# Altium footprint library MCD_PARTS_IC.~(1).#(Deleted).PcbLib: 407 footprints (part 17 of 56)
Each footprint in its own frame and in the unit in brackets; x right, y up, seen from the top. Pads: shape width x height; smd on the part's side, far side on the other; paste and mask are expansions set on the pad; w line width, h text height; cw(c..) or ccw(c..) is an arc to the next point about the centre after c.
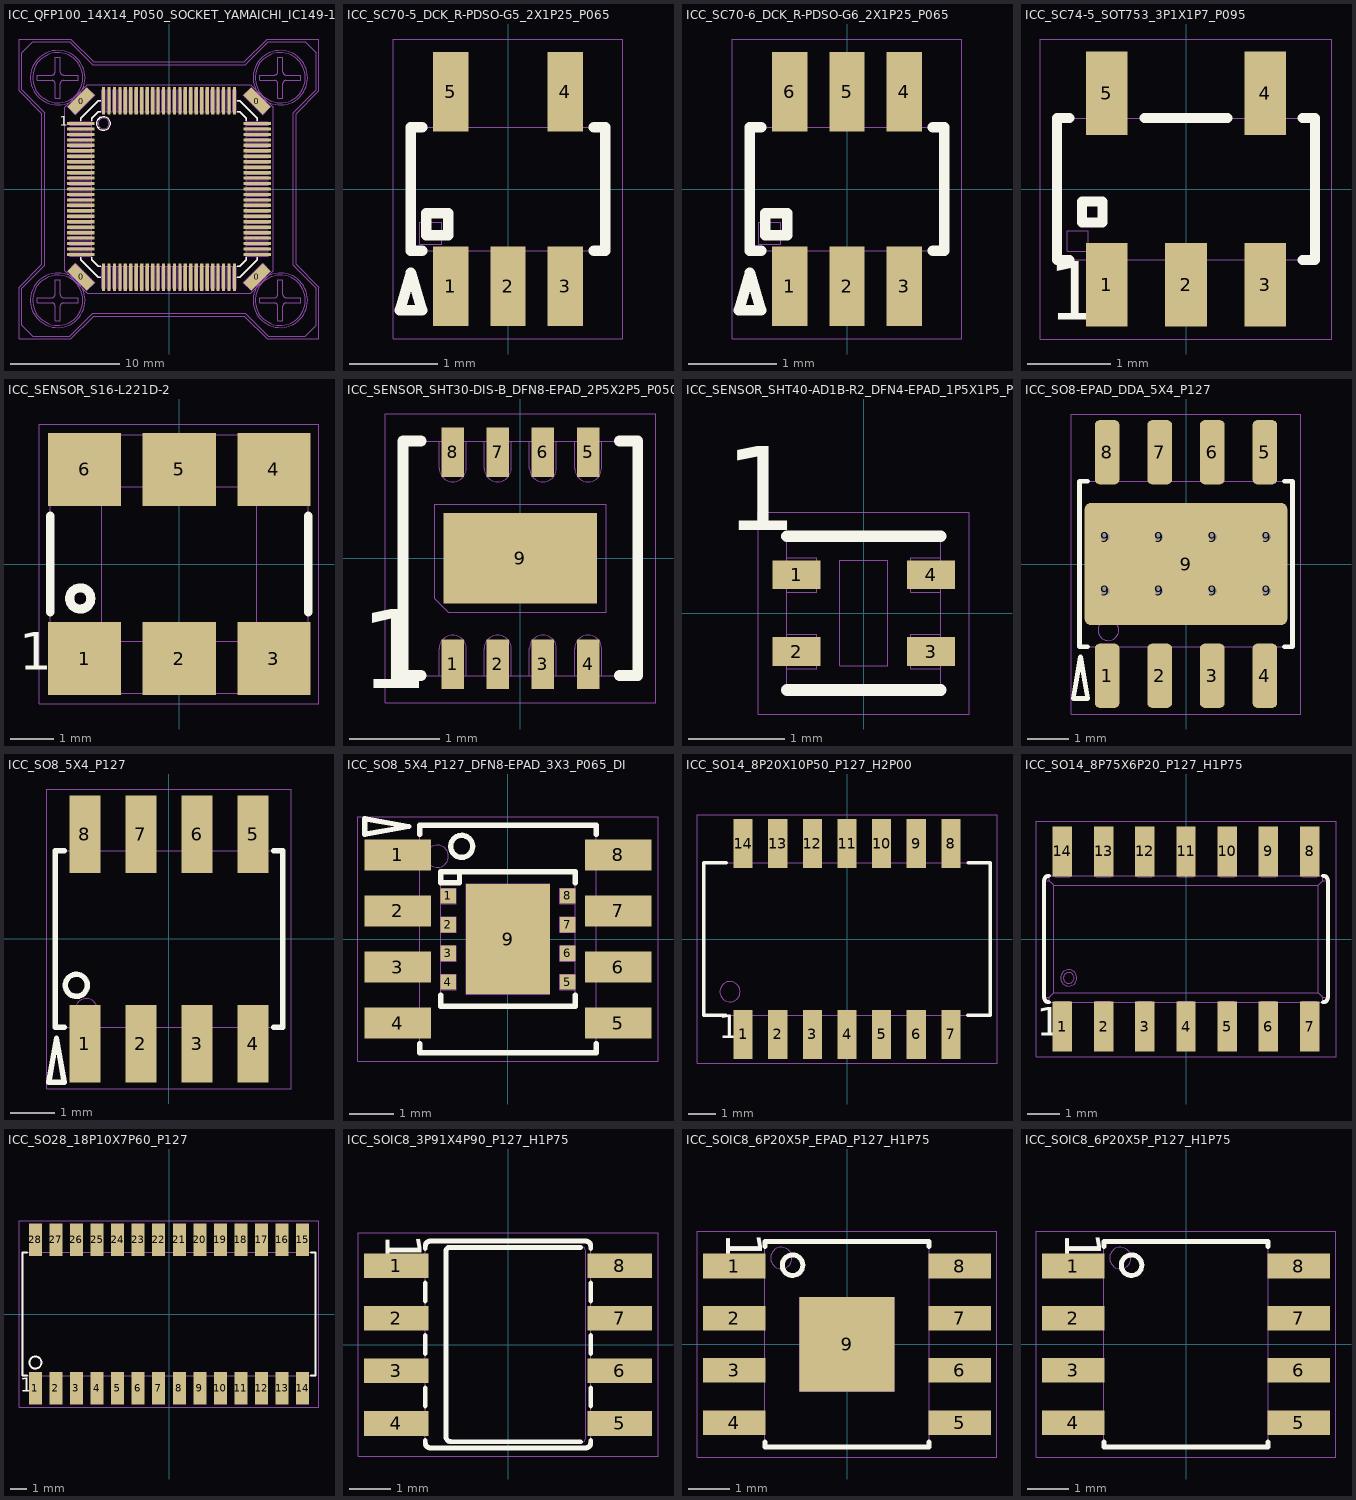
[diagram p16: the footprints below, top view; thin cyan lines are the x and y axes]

## ICC_QFP100_14X14_P050_SOCKET_YAMAICHI_IC149-100-025-B5__CUSTOM-FOR-DI__MB1581A [mm]
height 13.2
pads (104):
  rect 1x2.5 smd rot 45 mask+0.05: 0(-8.061,-8.061) 0(8.061,8.061)
  rect 1x2.5 smd rot 135 mask+0.05: 0(-8.061,8.061) 0(8.061,-8.061)
  rect 2.5x0.3 smd mask+0.05: 1(-8.1,6) 2(-8.1,5.5) 3(-8.1,5) 4(-8.1,4.5) 5(-8.1,4) 6(-8.1,3.5) 7(-8.1,3) 8(-8.1,2.5) 9(-8.1,2) 10(-8.1,1.5) 11(-8.1,1) 12(-8.1,0.5) 13(-8.1,0) 14(-8.1,-0.5) 15(-8.1,-1) 16(-8.1,-1.5) 17(-8.1,-2) 18(-8.1,-2.5) 19(-8.1,-3) 20(-8.1,-3.5) 21(-8.1,-4) 22(-8.1,-4.5) 23(-8.1,-5) 24(-8.1,-5.5) 25(-8.1,-6) 51(8.1,-6) 52(8.1,-5.5) 53(8.1,-5) 54(8.1,-4.5) 55(8.1,-4) 56(8.1,-3.5) 57(8.1,-3) 58(8.1,-2.5) 59(8.1,-2) 60(8.1,-1.5) 61(8.1,-1) 62(8.1,-0.5) 63(8.1,0) 64(8.1,0.5) 65(8.1,1) 66(8.1,1.5) 67(8.1,2) 68(8.1,2.5) 69(8.1,3) 70(8.1,3.5) 71(8.1,4) 72(8.1,4.5) 73(8.1,5) 74(8.1,5.5) 75(8.1,6)
  rect 0.3x2.5 smd mask+0.05: 26(-6,-8.1) 27(-5.5,-8.1) 28(-5,-8.1) 29(-4.5,-8.1) 30(-4,-8.1) 31(-3.5,-8.1) 32(-3,-8.1) 33(-2.5,-8.1) 34(-2,-8.1) 35(-1.5,-8.1) 36(-1,-8.1) 37(-0.5,-8.1) 38(0,-8.1) 39(0.5,-8.1) 40(1,-8.1) 41(1.5,-8.1) 42(2,-8.1) 43(2.5,-8.1) 44(3,-8.1) 45(3.5,-8.1) 46(4,-8.1) 47(4.5,-8.1) 48(5,-8.1) 49(5.5,-8.1) 50(6,-8.1) 76(6,8.1) 77(5.5,8.1) 78(5,8.1) 79(4.5,8.1) 80(4,8.1) 81(3.5,8.1) 82(3,8.1) 83(2.5,8.1) 84(2,8.1) 85(1.5,8.1) 86(1,8.1) 87(0.5,8.1) 88(0,8.1) 89(-0.5,8.1) 90(-1,8.1) 91(-1.5,8.1) 92(-2,8.1) 93(-2.5,8.1) 94(-3,8.1) 95(-3.5,8.1) 96(-4,8.1) 97(-4.5,8.1) 98(-5,8.1) 99(-5.5,8.1) 100(-6,8.1)
Top Overlay:
  circle w0.12: c-6,6 r0.625
  lines w0.12: -8.1,-6.275 -8.1,-6.475 -6.475,-8.1 -6.275,-8.1 ; -8.1,6.275 -8.1,6.475 -6.475,8.1 -6.275,8.1 ; -7.1,-6.275 -7.1,-6.5 -6.5,-7.1 -6.275,-7.1 ; -7.1,6.275 -7.1,6.5 -6.5,7.1 -6.275,7.1 ; 6.275,-8.1 6.475,-8.1 8.1,-6.475 8.1,-6.275 ; 6.275,-7.1 6.5,-7.1 7.1,-6.5 7.1,-6.275 ; 6.275,7.1 6.5,7.1 7.1,6.5 7.1,6.275 ; 6.275,8.1 6.475,8.1 8.1,6.475 8.1,6.275
  text "1" at -10,5.5 h1.5
M7-Top Info:
  lines w0.01: -13.75,-13.75 -13.75,-9.1 -13.75,-9 -11.65,-6.9 -11.65,0 -11.65,6.9 -13.75,9 -13.75,9.1 -13.75,13.75 -9.1,13.75 -9,13.75 -6.9,11.65 0,11.65 6.9,11.65 9,13.75 9.1,13.75 13.75,13.75 13.75,9.1 13.75,9 11.65,6.9 11.65,0 11.65,-6.9 13.75,-9 13.75,-9.1 13.75,-13.75 9.1,-13.75 9,-13.75 6.9,-11.65 0,-11.65 -6.9,-11.65 -9,-13.75 -9.1,-13.75 -13.75,-13.75 ; -9.575,-7.475 -9.575,-6.2 -9.575,6.225 -9.575,7.475 -7.475,9.575 -6.2,9.575 6.225,9.575 7.475,9.575 9.575,7.475 9.575,6.2 9.575,-6.225 9.575,-7.475 7.475,-9.575 -6.225,-9.575 -7.475,-9.575 -9.575,-7.475
  text "AREA AUTHORIZED FOR COMPONENTS LOWER THAN 3.5MM" at -13.2,10.275 h0.7
  text "AREA AUTHORIZED FOR COMPONENTS LOWER THAN 3.5MM" at -10.275,-13.2 h0.7
  text "AREA AUTHORIZED FOR COMPONENTS LOWER THAN 3.5MM" at 10.275,13.2 h0.7
  text "AREA AUTHORIZED FOR COMPONENTS LOWER THAN 3.5MM" at 13.2,-10.275 h0.7
M14-Top Assembly:
  drawing of 869 lines, arcs and shapes, not listed
  text "100" at -5.325,8.075 h1
  text "76" at 6.45,8.075 h1
  text "75" at 8.075,5.525 h1
  text "51" at 8.075,-6.4 h1
  text "50" at 5.55,-8.075 h1
  text "26" at -6.45,-8.075 h1
  text "1" at -8.075,6.125 h1
  text "'.Designator'" at -2,-0.5 h0.75
  text "25" at -8.075,-5.55 h1
M16-Top Courtyard:
  lines w0.01: -13.75,-13.75 -9.1,-13.75 -9,-13.75 -6.9,-11.65 0,-11.65 6.9,-11.65 9,-13.75 9.1,-13.75 13.75,-13.75 13.75,-9.1 13.75,-9 11.65,-6.9 11.65,0 11.65,6.9 13.75,9 13.75,9.1 13.75,13.75 9.1,13.75 9,13.75 6.9,11.65 0,11.65 -6.9,11.65 -9,13.75 -9.1,13.75 -13.75,13.75 -13.75,9.1 -13.75,9 -11.65,6.9 -11.65,0 -11.65,-6.9 -13.75,-9 -13.75,-9.1 -13.75,-13.75 ; -9.575,-7.475 -7.475,-9.575 -6.225,-9.575 7.475,-9.575 9.575,-7.475 9.575,-6.225 9.575,6.2 9.575,7.475 7.475,9.575 6.225,9.575 -6.2,9.575 -7.475,9.575 -9.575,7.475 -9.575,6.225 -9.575,-6.2 -9.575,-7.475
  text "AREA AUTHORIZED FOR COMPONENTS LOWER THAN 3.5MM" at 13.2,-10.275 h0.7
  text "AREA AUTHORIZED FOR COMPONENTS LOWER THAN 3.5MM" at 10.275,13.2 h0.7
  text "AREA AUTHORIZED FOR COMPONENTS LOWER THAN 3.5MM" at -10.275,-13.2 h0.7
  text "AREA AUTHORIZED FOR COMPONENTS LOWER THAN 3.5MM" at -13.2,10.275 h0.7
3D body "LQFP100_05.STEP": height 7.1, standoff 5.5, extent -8,-8 8,8
3D body: height 11, standoff 3.5, extent 0,-13.5 13.5,13.5
3D body: height 11, standoff 3.5, extent -13.5,-13.5 0,13.5
3D body: height 0.2, standoff 0, extent -9.1,3.85 -8.1,4.15
3D body: height 0.2, standoff 0, extent -9.1,4.35 -8.1,4.65
3D body: height 0.2, standoff 0, extent -9.1,4.85 -8.1,5.15
3D body: height 0.2, standoff 0, extent -9.1,5.35 -8.1,5.65
3D body: height 0.2, standoff 0, extent -9.1,5.85 -8.1,6.15
3D body: height 0.2, standoff 0, extent -9.1,1.35 -8.1,1.65
3D body: height 0.2, standoff 0, extent -9.1,1.85 -8.1,2.15
3D body: height 0.2, standoff 0, extent -9.1,2.35 -8.1,2.65
3D body: height 0.2, standoff 0, extent -9.1,2.85 -8.1,3.15
3D body: height 0.2, standoff 0, extent -9.1,3.35 -8.1,3.65
3D body: height 0.2, standoff 0, extent -9.1,-1.15 -8.1,-0.85
3D body: height 0.2, standoff 0, extent -9.1,-0.65 -8.1,-0.35
3D body: height 0.2, standoff 0, extent -9.1,-0.15 -8.1,0.15
3D body: height 0.2, standoff 0, extent -9.1,0.35 -8.1,0.65
3D body: height 0.2, standoff 0, extent -9.1,0.85 -8.1,1.15
3D body: height 0.2, standoff 0, extent -9.1,-3.65 -8.1,-3.35
3D body: height 0.2, standoff 0, extent -9.1,-3.15 -8.1,-2.85
3D body: height 0.2, standoff 0, extent -9.1,-2.65 -8.1,-2.35
3D body: height 0.2, standoff 0, extent -9.1,-2.15 -8.1,-1.85
3D body: height 0.2, standoff 0, extent -9.1,-1.65 -8.1,-1.35
3D body: height 0.2, standoff 0, extent -9.1,-6.15 -8.1,-5.85
3D body: height 0.2, standoff 0, extent -9.1,-5.65 -8.1,-5.35
3D body: height 0.2, standoff 0, extent -9.1,-5.15 -8.1,-4.85
3D body: height 0.2, standoff 0, extent -9.1,-4.65 -8.1,-4.35
3D body: height 0.2, standoff 0, extent -9.1,-4.15 -8.1,-3.85
3D body: height 0.2, standoff 0, extent -4.15,-9.1 -3.85,-8.1
3D body: height 0.2, standoff 0, extent -4.65,-9.1 -4.35,-8.1
3D body: height 0.2, standoff 0, extent -5.15,-9.1 -4.85,-8.1
3D body: height 0.2, standoff 0, extent -5.65,-9.1 -5.35,-8.1
3D body: height 0.2, standoff 0, extent -6.15,-9.1 -5.85,-8.1
3D body: height 0.2, standoff 0, extent -1.65,-9.1 -1.35,-8.1
3D body: height 0.2, standoff 0, extent -2.15,-9.1 -1.85,-8.1
3D body: height 0.2, standoff 0, extent -2.65,-9.1 -2.35,-8.1
3D body: height 0.2, standoff 0, extent -3.15,-9.1 -2.85,-8.1
3D body: height 0.2, standoff 0, extent -3.65,-9.1 -3.35,-8.1
3D body: height 0.2, standoff 0, extent 0.85,-9.1 1.15,-8.1
3D body: height 0.2, standoff 0, extent 0.35,-9.1 0.65,-8.1
3D body: height 0.2, standoff 0, extent -0.15,-9.1 0.15,-8.1
3D body: height 0.2, standoff 0, extent -0.65,-9.1 -0.35,-8.1
3D body: height 0.2, standoff 0, extent -1.15,-9.1 -0.85,-8.1
3D body: height 0.2, standoff 0, extent 3.35,-9.1 3.65,-8.1
3D body: height 0.2, standoff 0, extent 2.85,-9.1 3.15,-8.1
3D body: height 0.2, standoff 0, extent 2.35,-9.1 2.65,-8.1
3D body: height 0.2, standoff 0, extent 1.85,-9.1 2.15,-8.1
3D body: height 0.2, standoff 0, extent 1.35,-9.1 1.65,-8.1
3D body: height 0.2, standoff 0, extent 5.85,-9.1 6.15,-8.1
3D body: height 0.2, standoff 0, extent 5.35,-9.1 5.65,-8.1
3D body: height 0.2, standoff 0, extent 4.85,-9.1 5.15,-8.1
3D body: height 0.2, standoff 0, extent 4.35,-9.1 4.65,-8.1
3D body: height 0.2, standoff 0, extent 3.85,-9.1 4.15,-8.1
3D body: height 0.2, standoff 0, extent 8.1,-4.15 9.1,-3.85
3D body: height 0.2, standoff 0, extent 8.1,-4.65 9.1,-4.35
3D body: height 0.2, standoff 0, extent 8.1,-5.15 9.1,-4.85
3D body: height 0.2, standoff 0, extent 8.1,-5.65 9.1,-5.35
3D body: height 0.2, standoff 0, extent 8.1,-6.15 9.1,-5.85
3D body: height 0.2, standoff 0, extent 8.1,-1.65 9.1,-1.35
3D body: height 0.2, standoff 0, extent 8.1,-2.15 9.1,-1.85
3D body: height 0.2, standoff 0, extent 8.1,-2.65 9.1,-2.35
3D body: height 0.2, standoff 0, extent 8.1,-3.15 9.1,-2.85
3D body: height 0.2, standoff 0, extent 8.1,-3.65 9.1,-3.35
3D body: height 0.2, standoff 0, extent 8.1,0.85 9.1,1.15
3D body: height 0.2, standoff 0, extent 8.1,0.35 9.1,0.65
3D body: height 0.2, standoff 0, extent 8.1,-0.15 9.1,0.15
3D body: height 0.2, standoff 0, extent 8.1,-0.65 9.1,-0.35
3D body: height 0.2, standoff 0, extent 8.1,-1.15 9.1,-0.85
3D body: height 0.2, standoff 0, extent 8.1,3.35 9.1,3.65
3D body: height 0.2, standoff 0, extent 8.1,2.85 9.1,3.15
3D body: height 0.2, standoff 0, extent 8.1,2.35 9.1,2.65
3D body: height 0.2, standoff 0, extent 8.1,1.85 9.1,2.15
3D body: height 0.2, standoff 0, extent 8.1,1.35 9.1,1.65
3D body: height 0.2, standoff 0, extent 8.1,5.85 9.1,6.15
3D body: height 0.2, standoff 0, extent 8.1,5.35 9.1,5.65
3D body: height 0.2, standoff 0, extent 8.1,4.85 9.1,5.15
3D body: height 0.2, standoff 0, extent 8.1,4.35 9.1,4.65
3D body: height 0.2, standoff 0, extent 8.1,3.85 9.1,4.15
3D body: height 0.2, standoff 0, extent 3.85,8.1 4.15,9.1
3D body: height 0.2, standoff 0, extent 4.35,8.1 4.65,9.1
3D body: height 0.2, standoff 0, extent 4.85,8.1 5.15,9.1
3D body: height 0.2, standoff 0, extent 5.35,8.1 5.65,9.1
3D body: height 0.2, standoff 0, extent 5.85,8.1 6.15,9.1
3D body: height 0.2, standoff 0, extent 1.35,8.1 1.65,9.1
3D body: height 0.2, standoff 0, extent 1.85,8.1 2.15,9.1
3D body: height 0.2, standoff 0, extent 2.35,8.1 2.65,9.1
3D body: height 0.2, standoff 0, extent 2.85,8.1 3.15,9.1
3D body: height 0.2, standoff 0, extent 3.35,8.1 3.65,9.1
3D body: height 0.2, standoff 0, extent -1.15,8.1 -0.85,9.1
3D body: height 0.2, standoff 0, extent -0.65,8.1 -0.35,9.1
3D body: height 0.2, standoff 0, extent -0.15,8.1 0.15,9.1
3D body: height 0.2, standoff 0, extent 0.35,8.1 0.65,9.1
3D body: height 0.2, standoff 0, extent 0.85,8.1 1.15,9.1
3D body: height 0.2, standoff 0, extent -3.65,8.1 -3.35,9.1
3D body: height 0.2, standoff 0, extent -3.15,8.1 -2.85,9.1
3D body: height 0.2, standoff 0, extent -2.65,8.1 -2.35,9.1
3D body: height 0.2, standoff 0, extent -2.15,8.1 -1.85,9.1
3D body: height 0.2, standoff 0, extent -1.65,8.1 -1.35,9.1
3D body: height 0.2, standoff 0, extent -4.15,8.1 -3.85,9.1
3D body: height 0.2, standoff 0, extent -4.65,8.1 -4.35,9.1
3D body: height 0.2, standoff 0, extent -5.15,8.1 -4.85,9.1
3D body: height 0.2, standoff 0, extent -5.65,8.1 -5.35,9.1
3D body: height 13.2, standoff 12.2, extent -10.2,10.2 -7.9,12.5
3D body: height 13.2, standoff 12.2, extent -10.2,7.9 -7.9,10.2
3D body: height 13.2, standoff 12.2, extent -12.5,7.9 -10.2,10.2
3D body: height 13.2, standoff 12.2, extent -12.5,10.2 -10.2,12.5
3D body: height 12.2, standoff 11.2, extent -12.5,7.9 -7.9,12.5
3D body: height 11.2, standoff 11, extent -12.7,7.703 -7.7,12.697
3D body: height 0.2, standoff 0, extent -6.15,8.1 -5.85,9.1
3D body: height 11.2, standoff 11, extent 7.7,7.703 12.7,12.697
3D body: height 12.2, standoff 11.2, extent 7.9,7.9 12.5,12.5
3D body: height 13.2, standoff 12.2, extent 7.9,10.2 10.2,12.5
3D body: height 13.2, standoff 12.2, extent 7.9,7.9 10.2,10.2
3D body: height 13.2, standoff 12.2, extent 10.2,7.9 12.5,10.2
3D body: height 13.2, standoff 12.2, extent 10.2,10.2 12.5,12.5
3D body: height 11.2, standoff 11, extent 7.7,-12.697 12.7,-7.703
3D body: height 12.2, standoff 11.2, extent 7.9,-12.5 12.5,-7.9
3D body: height 13.2, standoff 12.2, extent 7.9,-10.2 10.2,-7.9
3D body: height 13.2, standoff 12.2, extent 7.9,-12.5 10.2,-10.2
3D body: height 13.2, standoff 12.2, extent 10.2,-12.5 12.5,-10.2
3D body: height 13.2, standoff 12.2, extent 10.2,-10.2 12.5,-7.9
3D body: height 11.2, standoff 11, extent -12.7,-12.697 -7.7,-7.703
3D body: height 12.2, standoff 11.2, extent -12.5,-12.5 -7.9,-7.9
3D body: height 13.2, standoff 12.2, extent -12.5,-10.2 -10.2,-7.9
3D body: height 13.2, standoff 12.2, extent -12.5,-12.5 -10.2,-10.2
3D body: height 13.2, standoff 12.2, extent -10.2,-12.5 -7.9,-10.2
3D body: height 13.2, standoff 12.2, extent -10.2,-10.2 -7.9,-7.9
3D body: height 3.5, standoff 0, extent -9.297,6.825 -6.823,9.3
3D body: height 3.5, standoff 0, extent 6.825,6.823 9.3,9.297
3D body: height 3.5, standoff 0, extent 6.823,-9.3 9.297,-6.825
3D body: height 3.5, standoff 0, extent -9.3,-9.297 -6.825,-6.823
3D body: height 5.5, standoff 0, extent -8.1,-8.1 8.1,8.1
3D body: height 3.5, standoff 0.2, extent -6.15,8.1 -5.85,8.35
3D body: height 3.5, standoff 0.2, extent -5.65,8.1 -5.35,8.35
3D body: height 3.5, standoff 0.2, extent -5.15,8.1 -4.85,8.35
3D body: height 3.5, standoff 0.2, extent -4.65,8.1 -4.35,8.35
3D body: height 3.5, standoff 0.2, extent -4.15,8.1 -3.85,8.35
3D body: height 3.5, standoff 0.2, extent -1.65,8.1 -1.35,8.35
3D body: height 3.5, standoff 0.2, extent -2.15,8.1 -1.85,8.35
3D body: height 3.5, standoff 0.2, extent -2.65,8.1 -2.35,8.35
3D body: height 3.5, standoff 0.2, extent -3.15,8.1 -2.85,8.35
3D body: height 3.5, standoff 0.2, extent -3.65,8.1 -3.35,8.35
3D body: height 3.5, standoff 0.2, extent 0.85,8.1 1.15,8.35
3D body: height 3.5, standoff 0.2, extent 0.35,8.1 0.65,8.35
3D body: height 3.5, standoff 0.2, extent -0.15,8.1 0.15,8.35
3D body: height 3.5, standoff 0.2, extent -0.65,8.1 -0.35,8.35
3D body: height 3.5, standoff 0.2, extent -1.15,8.1 -0.85,8.35
3D body: height 3.5, standoff 0.2, extent 3.35,8.1 3.65,8.35
3D body: height 3.5, standoff 0.2, extent 2.85,8.1 3.15,8.35
3D body: height 3.5, standoff 0.2, extent 2.35,8.1 2.65,8.35
3D body: height 3.5, standoff 0.2, extent 1.85,8.1 2.15,8.35
3D body: height 3.5, standoff 0.2, extent 1.35,8.1 1.65,8.35
3D body: height 3.5, standoff 0.2, extent 5.85,8.1 6.15,8.35
3D body: height 3.5, standoff 0.2, extent 5.35,8.1 5.65,8.35
3D body: height 3.5, standoff 0.2, extent 4.85,8.1 5.15,8.35
3D body: height 3.5, standoff 0.2, extent 4.35,8.1 4.65,8.35
3D body: height 3.5, standoff 0.2, extent 3.85,8.1 4.15,8.35
3D body: height 3.5, standoff 0.2, extent 8.1,3.85 8.35,4.15
3D body: height 3.5, standoff 0.2, extent 8.1,4.35 8.35,4.65
3D body: height 3.5, standoff 0.2, extent 8.1,4.85 8.35,5.15
3D body: height 3.5, standoff 0.2, extent 8.1,5.35 8.35,5.65
3D body: height 3.5, standoff 0.2, extent 8.1,5.85 8.35,6.15
3D body: height 3.5, standoff 0.2, extent 8.1,1.35 8.35,1.65
3D body: height 3.5, standoff 0.2, extent 8.1,1.85 8.35,2.15
3D body: height 3.5, standoff 0.2, extent 8.1,2.35 8.35,2.65
3D body: height 3.5, standoff 0.2, extent 8.1,2.85 8.35,3.15
3D body: height 3.5, standoff 0.2, extent 8.1,3.35 8.35,3.65
3D body: height 3.5, standoff 0.2, extent 8.1,-1.15 8.35,-0.85
3D body: height 3.5, standoff 0.2, extent 8.1,-0.65 8.35,-0.35
3D body: height 3.5, standoff 0.2, extent 8.1,-0.15 8.35,0.15
3D body: height 3.5, standoff 0.2, extent 8.1,0.35 8.35,0.65
3D body: height 3.5, standoff 0.2, extent 8.1,0.85 8.35,1.15
3D body: height 3.5, standoff 0.2, extent 8.1,-3.65 8.35,-3.35
3D body: height 3.5, standoff 0.2, extent 8.1,-3.15 8.35,-2.85
3D body: height 3.5, standoff 0.2, extent 8.1,-2.65 8.35,-2.35
3D body: height 3.5, standoff 0.2, extent 8.1,-2.15 8.35,-1.85
3D body: height 3.5, standoff 0.2, extent 8.1,-1.65 8.35,-1.35
3D body: height 3.5, standoff 0.2, extent 8.1,-6.15 8.35,-5.85
3D body: height 3.5, standoff 0.2, extent 8.1,-5.65 8.35,-5.35
3D body: height 3.5, standoff 0.2, extent 8.1,-5.15 8.35,-4.85
3D body: height 3.5, standoff 0.2, extent 8.1,-4.65 8.35,-4.35
3D body: height 3.5, standoff 0.2, extent 8.1,-4.15 8.35,-3.85
3D body: height 3.5, standoff 0.2, extent 3.85,-8.35 4.15,-8.1
3D body: height 3.5, standoff 0.2, extent 4.35,-8.35 4.65,-8.1
3D body: height 3.5, standoff 0.2, extent 4.85,-8.35 5.15,-8.1
3D body: height 3.5, standoff 0.2, extent 5.35,-8.35 5.65,-8.1
3D body: height 3.5, standoff 0.2, extent 5.85,-8.35 6.15,-8.1
3D body: height 3.5, standoff 0.2, extent 1.35,-8.35 1.65,-8.1
3D body: height 3.5, standoff 0.2, extent 1.85,-8.35 2.15,-8.1
3D body: height 3.5, standoff 0.2, extent 2.35,-8.35 2.65,-8.1
3D body: height 3.5, standoff 0.2, extent 2.85,-8.35 3.15,-8.1
3D body: height 3.5, standoff 0.2, extent 3.35,-8.35 3.65,-8.1
3D body: height 3.5, standoff 0.2, extent -1.15,-8.35 -0.85,-8.1
3D body: height 3.5, standoff 0.2, extent -0.65,-8.35 -0.35,-8.1
3D body: height 3.5, standoff 0.2, extent -0.15,-8.35 0.15,-8.1
3D body: height 3.5, standoff 0.2, extent 0.35,-8.35 0.65,-8.1
3D body: height 3.5, standoff 0.2, extent 0.85,-8.35 1.15,-8.1
3D body: height 3.5, standoff 0.2, extent -3.65,-8.35 -3.35,-8.1
3D body: height 3.5, standoff 0.2, extent -3.15,-8.35 -2.85,-8.1
3D body: height 3.5, standoff 0.2, extent -2.65,-8.35 -2.35,-8.1
3D body: height 3.5, standoff 0.2, extent -2.15,-8.35 -1.85,-8.1
3D body: height 3.5, standoff 0.2, extent -1.65,-8.35 -1.35,-8.1
3D body: height 3.5, standoff 0.2, extent -6.15,-8.35 -5.85,-8.1
3D body: height 3.5, standoff 0.2, extent -5.65,-8.35 -5.35,-8.1
3D body: height 3.5, standoff 0.2, extent -5.15,-8.35 -4.85,-8.1
3D body: height 3.5, standoff 0.2, extent -4.65,-8.35 -4.35,-8.1
3D body: height 3.5, standoff 0.2, extent -4.15,-8.35 -3.85,-8.1
3D body: height 3.5, standoff 0.2, extent -8.35,-4.15 -8.1,-3.85
3D body: height 3.5, standoff 0.2, extent -8.35,-4.65 -8.1,-4.35
3D body: height 3.5, standoff 0.2, extent -8.35,-5.15 -8.1,-4.85
3D body: height 3.5, standoff 0.2, extent -8.35,-5.65 -8.1,-5.35
3D body: height 3.5, standoff 0.2, extent -8.35,-6.15 -8.1,-5.85
3D body: height 3.5, standoff 0.2, extent -8.35,-1.65 -8.1,-1.35
3D body: height 3.5, standoff 0.2, extent -8.35,-2.15 -8.1,-1.85
3D body: height 3.5, standoff 0.2, extent -8.35,-2.65 -8.1,-2.35
3D body: height 3.5, standoff 0.2, extent -8.35,-3.15 -8.1,-2.85
3D body: height 3.5, standoff 0.2, extent -8.35,-3.65 -8.1,-3.35
3D body: height 3.5, standoff 0.2, extent -8.35,0.85 -8.1,1.15
3D body: height 3.5, standoff 0.2, extent -8.35,0.35 -8.1,0.65
3D body: height 3.5, standoff 0.2, extent -8.35,-0.15 -8.1,0.15
3D body: height 3.5, standoff 0.2, extent -8.35,-0.65 -8.1,-0.35
3D body: height 3.5, standoff 0.2, extent -8.35,-1.15 -8.1,-0.85
3D body: height 3.5, standoff 0.2, extent -8.35,3.35 -8.1,3.65
3D body: height 3.5, standoff 0.2, extent -8.35,2.85 -8.1,3.15
3D body: height 3.5, standoff 0.2, extent -8.35,2.35 -8.1,2.65
3D body: height 3.5, standoff 0.2, extent -8.35,1.85 -8.1,2.15
3D body: height 3.5, standoff 0.2, extent -8.35,1.35 -8.1,1.65
3D body: height 3.5, standoff 0.2, extent -8.35,5.85 -8.1,6.15
3D body: height 3.5, standoff 0.2, extent -8.35,5.35 -8.1,5.65
3D body: height 3.5, standoff 0.2, extent -8.35,4.85 -8.1,5.15
3D body: height 3.5, standoff 0.2, extent -8.35,4.35 -8.1,4.65
3D body: height 3.5, standoff 0.2, extent -8.35,3.85 -8.1,4.15

## ICC_SC70-5_DCK_R-PDSO-G5_2X1P25_P065 [mm] "MCD-02032"
height 1.1
pads (5):
  rect 0.4x0.9 smd mask+0.05: 1(-0.65,-1.1) 2(0,-1.1) 3(0.65,-1.1) 4(0.65,1.1) 5(-0.65,1.1)
Top Overlay:
  lines w0.12: -0.975,-0.7 -1.1,-0.7 -1.1,0.7 -0.975,0.7 ; 0.975,-0.7 1.1,-0.7 1.1,0.7 0.975,0.7 ; -1.225,-1.375 -0.975,-1.375 -1.1,-0.95 -1.225,-1.375 ; -0.925,-0.525 -0.925,-0.275 -0.675,-0.275 -0.675,-0.525 -0.925,-0.525
M14-Top Assembly:
  lines w0.01: -0.8,-0.7 -0.8,-1.2 -0.5,-1.2 -0.5,-0.7 ; -0.8,0.7 -0.8,1.2 -0.5,1.2 -0.5,0.7 ; -0.15,-0.7 -0.15,-1.2 0.15,-1.2 0.15,-0.7 ; 0.5,-0.7 0.5,-1.2 0.8,-1.2 0.8,-0.7 ; 0.5,0.7 0.5,1.2 0.8,1.2 0.8,0.7 ; -1.1,-0.7 -1.1,0.7 1.1,0.7 1.1,-0.7 -1.1,-0.7 ; -1,-0.625 -1,-0.375 -0.75,-0.375 -0.75,-0.625 -1,-0.625
  text "'.Designator'" at -2,-0.5 h0.75
  text "1" at -0.725,-1.15 h0.6
  text "2" at -0.125,-1.15 h0.6
  text "3" at 0.525,-1.15 h0.6
  text "4" at 0.525,0.75 h0.6
  text "5" at -0.775,0.75 h0.6
M16-Top Courtyard:
  lines w0.01: -1.3,-1.7 1.3,-1.7 1.3,1.7 -1.3,1.7 -1.3,-1.7
3D body: height 1.1, standoff 0, extent -1.1,-0.7 1.1,0.7
3D body "SC70-5.STEP": height 0.97, standoff 0, extent -1,-1.1 1,1.1
3D body: height 0.98, standoff 0.97, extent -0.874,-0.5 -0.575,-0.2

## ICC_SC70-6_DCK_R-PDSO-G6_2X1P25_P065 [mm]
height 1.1
pads (6):
  rect 0.4x0.9 smd mask+0.05: 1(-0.65,-1.1) 2(0,-1.1) 3(0.65,-1.1) 4(0.65,1.1) 5(0,1.1) 6(-0.65,1.1)
Top Overlay:
  lines w0.12: -0.975,-0.7 -1.1,-0.7 -1.1,0.7 -0.975,0.7 ; 0.975,-0.7 1.1,-0.7 1.1,0.7 0.975,0.7 ; -1.225,-1.375 -0.975,-1.375 -1.1,-0.95 -1.225,-1.375 ; -0.925,-0.525 -0.925,-0.275 -0.675,-0.275 -0.675,-0.525 -0.925,-0.525
M14-Top Assembly:
  lines w0.01: -0.8,-0.7 -0.8,-1.2 -0.5,-1.2 -0.5,-0.7 ; -0.8,0.7 -0.8,1.2 -0.5,1.2 -0.5,0.7 ; -0.15,-0.7 -0.15,-1.2 0.15,-1.2 0.15,-0.7 ; -0.15,0.7 -0.15,1.2 0.15,1.2 0.15,0.7 ; 0.5,-0.7 0.5,-1.2 0.8,-1.2 0.8,-0.7 ; 0.5,0.7 0.5,1.2 0.8,1.2 0.8,0.7 ; -1.1,-0.7 -1.1,0.7 1.1,0.7 1.1,-0.7 -1.1,-0.7 ; -1,-0.625 -1,-0.375 -0.75,-0.375 -0.75,-0.625 -1,-0.625
  text "'.Designator'" at -2,-0.5 h0.75
  text "1" at -0.725,-1.15 h0.6
  text "2" at -0.125,-1.15 h0.6
  text "3" at 0.525,-1.15 h0.6
  text "4" at 0.525,0.75 h0.6
  text "5" at -0.125,0.75 h0.6
  text "6" at -0.775,0.75 h0.6
M16-Top Courtyard:
  lines w0.01: -1.3,-1.7 1.3,-1.7 1.3,1.7 -1.3,1.7 -1.3,-1.7
3D body: height 1.11, standoff 1.1, extent -0.998,-0.625 -0.6,-0.225
3D body: height 1.1, standoff 0, extent -1.1,-0.7 1.1,0.7
3D body "SC70-6.STEP": height 0.95, standoff 0, extent -1,-1.05 1,1.05

## ICC_SC74-5_SOT753_3P1X1P7_P095 [mm] "MCD-02626"
height 1.1
pads (5):
  rect 0.5x1 smd mask+0.05: 1(-0.95,-1.15) 2(0,-1.15) 3(0.95,-1.15) 4(0.95,1.15) 5(-0.95,1.15)
Top Overlay:
  lines w0.12: -1.4,-0.85 -1.55,-0.85 -1.55,0.85 -1.4,0.85 ; -0.5,0.85 0.5,0.85 ; 1.4,-0.85 1.55,-0.85 1.55,0.85 1.4,0.85 ; -1.25,-0.4 -1,-0.4 -1,-0.15 -1.25,-0.15 -1.25,-0.4
  text "1" at -1.65,-1.8 h1.2
M14-Top Assembly:
  lines w0.01: -1.15,-0.85 -1.15,-1.5 -0.75,-1.5 -0.75,-0.85 ; -1.15,0.85 -1.15,1.5 -0.75,1.5 -0.75,0.85 ; -0.2,-0.85 -0.2,-1.5 0.2,-1.5 0.2,-0.85 ; 0.75,-0.85 0.75,-1.5 1.15,-1.5 1.15,-0.85 ; 0.75,0.85 0.75,1.5 1.15,1.5 1.15,0.85 ; -1.55,-0.85 1.55,-0.85 1.55,0.85 -1.55,0.85 -1.55,-0.85 ; -1.425,-0.75 -1.175,-0.75 -1.175,-0.5 -1.425,-0.5 -1.425,-0.75
  text "1" at -1.025,-1.375 h0.6
  text "5" at -1.075,1 h0.6
  text "4" at 0.8,1 h0.6
  text "3" at 0.85,-1.375 h0.6
  text "2" at -0.125,-1.375 h0.6
  text "'.Designator'" at -2,-0.5 h0.75
M16-Top Courtyard:
  lines w0.01: -1.75,-1.8 -1.75,1.8 1.75,1.8 1.75,-1.8 -1.75,-1.8
3D body "27707.stp": height 1.2, standoff 0, extent -1.45,-1.4 1.45,1.4

## ICC_SENSOR_S16-L221D-2 [mm] "MCD-01754"
height 2.8
pads (6):
  rect 1.7x1.7 smd: 1(-2.2,-2.2) 2(0,-2.2) 3(2.2,-2.2) 4(2.2,2.2) 5(0,2.2) 6(-2.2,2.2)
Top Overlay:
  circle w0.21: c-2.3,-0.8 r0.246
  lines w0.2: -3,-1.125 -3,1.125 ; 3,-1.125 3,1.125
  text "1" at -3.725,-2.75 h1.5
M14-Top Assembly:
  lines w0.01: -3,-3 -3,3 3,3 3,-3 -3,-3 ; -1.8,-1.8 -1.8,1.8 1.8,1.8 1.8,-1.8 -1.8,-1.8
  text "'.Designator'" at -2,-0.5 h0.75
M16-Top Courtyard:
  lines w0.01: -3.25,-3.25 3.25,-3.25 3.25,3.25 -3.25,3.25 -3.25,-3.25
3D body: height 2.8, standoff 0, extent -3,-3 3,3

## ICC_SENSOR_SHT30-DIS-B_DFN8-EPAD_2P5X2P5_P050 [mm] "MCD-02616"
height 1
pads (9):
  rect 0.25x0.55 smd mask+0.05: 1(-0.75,-1.175) 2(-0.25,-1.175) 3(0.25,-1.175) 4(0.75,-1.175) 5(0.75,1.175) 6(0.25,1.175) 7(-0.25,1.175) 8(-0.75,1.175)
  rect 1.7x1 smd mask+0.05: 9(0,0)
Top Overlay:
  lines w0.12: -1.1,-1.3 -1.3,-1.3 -1.3,1.3 -1.1,1.3 ; 1.1,-1.3 1.3,-1.3 1.3,1.3 1.1,1.3
  text "1" at -1.775,-1.725 h1.5
M14-Top Assembly:
  lines w0.01: -0.9,-1.3 -0.9,-1 cw(c-0.75,-1) -0.75,-0.85 cw(c-0.75,-1) -0.6,-1 -0.6,-1.3 ; -0.9,1.3 -0.9,1 ccw(c-0.75,1) -0.75,0.85 ccw(c-0.75,1) -0.6,1 -0.6,1.3 ; -0.4,-1.3 -0.4,-1 cw(c-0.25,-1) -0.25,-0.85 cw(c-0.25,-1) -0.1,-1 -0.1,-1.3 ; -0.4,1.3 -0.4,1 ccw(c-0.25,1) -0.25,0.85 ccw(c-0.25,1) -0.1,1 -0.1,1.3 ; 0.1,-1.3 0.1,-1 cw(c0.25,-1) 0.25,-0.85 cw(c0.25,-1) 0.4,-1 0.4,-1.3 ; 0.1,1.3 0.1,1 ccw(c0.25,1) 0.25,0.85 ccw(c0.25,1) 0.4,1 0.4,1.3 ; 0.6,-1.3 0.6,-1 cw(c0.75,-1) 0.75,-0.85 cw(c0.75,-1) 0.9,-1 0.9,-1.3 ; 0.6,1.3 0.6,1 ccw(c0.75,1) 0.75,0.85 ccw(c0.75,1) 0.9,1 0.9,1.3 ; -1.3,-1.3 1.3,-1.3 1.3,1.3 -1.3,1.3 -1.3,-1.3 ; -0.95,-0.45 -0.8,-0.6 0.95,-0.6 0.95,0.6 -0.95,0.6 -0.95,-0.45
  text "'.Designator'" at -2,-0.5 h0.75
  text "8" at -0.85,0.925 h0.5
  text "5" at 0.65,0.925 h0.5
  text "EP" at -0.25,-0.125 h0.5
  text "4" at 0.65,-1.25 h0.5
  text "1" at -0.825,-1.25 h0.5
M16-Top Courtyard:
  lines w0.01: -1.5,-1.6 -1.5,1.6 1.5,1.6 1.5,-1.6 -1.5,-1.6
3D body "User Library-SHT3x.STEP": height 0.9, standoff -0.01, extent -1.25,-1.26 1.25,1.26

## ICC_SENSOR_SHT40-AD1B-R2_DFN4-EPAD_1P5X1P5_P050 [mm] "MCD-03381"
height 0.6
pads (4):
  rect 0.5x0.3 smd mask+0.05: 1(-0.7,0.4) 2(-0.7,-0.4) 3(0.7,-0.4) 4(0.7,0.4)
Top Overlay:
  lines w0.12: -0.8,-0.8 0.8,-0.8 ; -0.8,0.8 0.8,0.8
  text "1" at -1.45,0.575 h1.5
M14-Top Assembly:
  lines w0.01: -0.8,-0.58 -0.49,-0.58 -0.49,-0.22 -0.8,-0.22 ; -0.8,0.22 -0.49,0.22 -0.49,0.58 -0.8,0.58 ; 0.8,-0.58 0.49,-0.58 0.49,-0.22 0.8,-0.22 ; 0.8,0.22 0.49,0.22 0.49,0.58 0.8,0.58 ; -0.8,-0.8 0.8,-0.8 0.8,0.8 -0.8,0.8 -0.8,-0.8 ; -0.25,-0.55 -0.25,0.55 0.25,0.55 0.25,-0.55 -0.25,-0.55
  text "1" at -0.725,0.25 h0.5
  text "EP" at -0.25,-0.125 h0.5
  text "'.Designator'" at -2,-0.525 h0.75
M16-Top Courtyard:
  lines w0.01: -1.1,-1.05 1.1,-1.05 1.1,1.05 -1.1,1.05 -1.1,-1.05
3D body: height 0.61, standoff 0.6, extent -0.625,0.475 -0.425,0.675
3D body: height 0.6, standoff 0, extent -0.8,-0.8 0.8,0.8
3D body: height 0.61, standoff 0.6, extent -0.298,-0.299 0.3,0.3

## ICC_SO8-EPAD_DDA_5X4_P127 [mm] "MCD-03695"
height 1.7
pads (17):
  rrect40% 0.6x1.55 smd mask+0.05: 1(-1.905,-2.7) 2(-0.635,-2.7) 3(0.635,-2.7) 4(1.905,-2.7) 5(1.905,2.7) 6(0.635,2.7) 7(-0.635,2.7) 8(-1.905,2.7)
  round 0.45 hole 0.2 mask+0.102: 9(-1.95,-0.65) 9(-1.95,0.65) 9(-0.65,-0.65) 9(-0.65,0.65) 9(0.65,-0.65) 9(0.65,0.65) 9(1.95,-0.65) 9(1.95,0.65)
  rrect10% 4.9x2.95 smd paste-10 mask+0.05: 9(0,0)
Top Overlay:
  lines w0.12: -2.375,-2 -2.575,-2 -2.575,2 -2.375,2 ; 2.375,-2 2.575,-2 2.575,2 2.375,2 ; -2.725,-3.25 -2.55,-2.25 -2.375,-3.25 -2.725,-3.25
Top Paste:
  rectangle: -1.17,-1.17 1.17,1.17
Top Solder:
  rectangle: -1.17,-1.17 1.17,1.17
M14-Top Assembly:
  circle w0.01: c-1.875,-1.6 r0.25
  lines w0.01: -2.575,-2 2.575,-2 2.575,2 -2.575,2 -2.575,-2 ; -2.1,-3 -2.1,-2 -1.7,-2 -1.7,-3 -2.1,-3 ; -2.1,2 -2.1,3 -1.7,3 -1.7,2 -2.1,2 ; -1.17,-1.17 -1.17,1.17 1.17,1.17 1.17,-1.17 -1.17,-1.17 ; -0.825,-3 -0.825,-2 -0.425,-2 -0.425,-3 -0.825,-3 ; -0.825,2 -0.825,3 -0.425,3 -0.425,2 -0.825,2 ; 0.425,-3 0.425,-2 0.825,-2 0.825,-3 0.425,-3 ; 0.425,2 0.425,3 0.825,3 0.825,2 0.425,2 ; 1.7,-3 1.7,-2 2.1,-2 2.1,-3 1.7,-3 ; 1.7,2 1.7,3 2.1,3 2.1,2 1.7,2
  text "1" at -2.1,-3.075 h1.5
  text "4" at 1.575,-3.1 h1.5
  text "5" at 1.6,2.1 h1.5
  text "8" at -2.225,2.125 h1.5
  text "'.Designator'" at -2,1 h0.75
  text "9" at -0.316,-0.474 h1.5
M16-Top Courtyard:
  lines w0.01: -2.775,-3.625 2.775,-3.625 2.775,3.625 -2.775,3.625 -2.775,-3.625
3D body "SO8.STEP": height 1.7, standoff 0, extent -2.45,-3 2.45,3

## ICC_SO8_5X4_P127 [mm]
height 1.75
pads (8):
  rect 0.7x1.75 smd mask+0.05: 1(-1.905,-2.375) 2(-0.635,-2.375) 3(0.635,-2.375) 4(1.905,-2.375) 5(1.905,2.375) 6(0.635,2.375) 7(-0.635,2.375) 8(-1.905,2.375)
Top Overlay:
  circle w0.12: c-2.1,-1.05 r0.25
  lines w0.12: -2.375,-2 -2.575,-2 -2.575,2 -2.375,2 ; 2.375,-2 2.575,-2 2.575,2 2.375,2 ; -2.725,-3.25 -2.375,-3.25 -2.55,-2.25 -2.725,-3.25
M14-Top Assembly:
  circle w0.01: c-1.875,-1.6 r0.25
  lines w0.01: -2.575,-2 -2.575,2 2.575,2 2.575,-2 -2.575,-2 ; -2.1,-3 -1.7,-3 -1.7,-2 -2.1,-2 -2.1,-3 ; -2.1,2 -1.7,2 -1.7,3 -2.1,3 -2.1,2 ; -0.825,-3 -0.425,-3 -0.425,-2 -0.825,-2 -0.825,-3 ; -0.825,2 -0.425,2 -0.425,3 -0.825,3 -0.825,2 ; 0.425,-3 0.825,-3 0.825,-2 0.425,-2 0.425,-3 ; 0.425,2 0.825,2 0.825,3 0.425,3 0.425,2 ; 1.7,-3 2.1,-3 2.1,-2 1.7,-2 1.7,-3 ; 1.7,2 2.1,2 2.1,3 1.7,3 1.7,2
  text "'.Designator'" at -2,-0.5 h0.75
  text "8" at -2.225,2.125 h1.5
  text "5" at 1.6,2.1 h1.5
  text "4" at 1.575,-3.1 h1.5
  text "1" at -2.1,-3.075 h1.5
M16-Top Courtyard:
  lines w0.01: -2.775,-3.4 -2.775,3.4 2.775,3.4 2.775,-3.4 -2.775,-3.4
3D body "SO8.STEP": height 1.7, standoff 0, extent -2.45,-3 2.45,3
3D body: height 1.75, standoff 0, extent -2.574,-1.999 2.574,1.999

## ICC_SO8_5X4_P127_DFN8-EPAD_3X3_P065_DI [mm]
height 1.75
pads (17):
  rect 1.5x0.7 smd mask+0.05: 1(-2.5,1.91) 2(-2.5,0.64) 3(-2.5,-0.63) 4(-2.5,-1.9) 5(2.5,-1.9) 6(2.5,-0.63) 7(2.5,0.64) 8(2.5,1.91)
  rect 0.35x0.35 smd mask+0.05: 1(-1.35,0.98) 2(-1.35,0.33) 3(-1.35,-0.32) 4(-1.35,-0.97) 5(1.35,-0.97) 6(1.35,-0.32) 7(1.35,0.33) 8(1.35,0.98)
  rect 1.9x2.5 smd mask+0.05: 9(0,0.005)
Top Overlay:
  circle w0.12: c-1.05,2.105 r0.25
  lines w0.12: -2,-2.37 -2,-2.57 2,-2.57 2,-2.37 ; -2,2.38 -2,2.58 2,2.58 2,2.38 ; -1.525,-1.27 -1.525,-1.52 1.525,-1.52 1.525,-1.27 ; -1.1,1.53 -1.1,1.28 -1.525,1.28 -1.525,1.53 1.525,1.53 1.525,1.28 ; -3.25,2.38 -3.25,2.73 -2.25,2.555 -3.25,2.38
M14-Top Assembly:
  circle w0.01: c-1.6,1.88 r0.25
  lines w0.01: -1.525,-1.145 -1.175,-1.145 -1.175,-0.795 -1.525,-0.795 ; -1.525,-0.495 -1.175,-0.495 -1.175,-0.145 -1.525,-0.145 ; -1.525,0.155 -1.175,0.155 -1.175,0.505 -1.525,0.505 ; -1.525,0.805 -1.175,0.805 -1.175,1.155 -1.525,1.155 ; 1.525,-1.145 1.175,-1.145 1.175,-0.795 1.525,-0.795 ; 1.525,-0.495 1.175,-0.495 1.175,-0.145 1.525,-0.145 ; 1.525,0.155 1.175,0.155 1.175,0.505 1.525,0.505 ; 1.525,0.805 1.175,0.805 1.175,1.155 1.525,1.155 ; -3,-2.095 -3,-1.695 -2,-1.695 -2,-2.095 -3,-2.095 ; -3,-0.82 -3,-0.42 -2,-0.42 -2,-0.82 -3,-0.82 ; -3,0.43 -3,0.83 -2,0.83 -2,0.43 -3,0.43 ; -3,1.705 -3,2.105 -2,2.105 -2,1.705 -3,1.705 ; -2,-2.57 -2,2.58 2,2.58 2,-2.57 -2,-2.57 ; -1.525,-1.52 1.525,-1.52 1.525,1.53 -1.525,1.53 -1.525,-1.52 ; -0.95,-1.245 0.95,-1.245 0.95,1.255 -0.95,1.255 -0.95,-1.245 ; 2,-2.095 2,-1.695 3,-1.695 3,-2.095 2,-2.095 ; 2,-0.82 2,-0.42 3,-0.42 3,-0.82 2,-0.82 ; 2,0.43 2,0.83 3,0.83 3,0.43 2,0.43 ; 2,1.705 2,2.105 3,2.105 3,1.705 2,1.705
  text "1" at -1.525,1.055 h0.5
  text "4" at -1.525,-0.845 h0.5
  text "EP" at -0.125,0.255 h0.5
  text "5" at 1.175,-0.87 h0.5
  text "8" at 1.175,1.08 h0.5
  text "'.Designator'" at -2,-0.5 h0.75
  text "8" at 2.125,2.23 h1.5
  text "5" at 2.1,-1.595 h1.5
  text "4" at -3.1,-1.57 h1.5
  text "1" at -3.075,2.105 h1.5
M16-Top Courtyard:
  lines w0.01: -3.4,-2.77 -3.4,2.78 3.4,2.78 3.4,-2.77 -3.4,-2.77
3D body "User Library-DFN8N_65.STEP": height 0.9, standoff 0, extent -1.5,-1.495 1.5,1.495
3D body "SO8.STEP": height 1.7, standoff 0, extent -3,-2.445 3,2.455

## ICC_SO14_8P20X10P50_P127_H2P00 [mm] "MCD-03722"
height 2
pads (14):
  rect 0.7x1.8 smd mask+0.05: 1(-3.81,-3.5) 2(-2.54,-3.5) 3(-1.27,-3.5) 4(0,-3.5) 5(1.27,-3.5) 6(2.54,-3.5) 7(3.81,-3.5) 8(3.81,3.5) 9(2.54,3.5) 10(1.27,3.5) 11(0,3.5) 12(-1.27,3.5) 13(-2.54,3.5) 14(-3.81,3.5)
Top Overlay:
  lines w0.12: -4.45,-2.8 -5.25,-2.8 -5.25,2.8 -4.425,2.8 ; 4.425,-2.8 5.25,-2.8 5.25,2.8 4.45,2.8
  text "1" at -4.7,-3.925 h1.5
M14-Top Assembly:
  circle w0.01: c-4.292,-1.933 r0.373
  lines w0.01: -4.06,2.8 -4.06,4.1 -3.56,4.1 -3.56,2.8 ; -4.06,-4.1 -4.06,-2.8 -4.06,-4.1 ; -4.06,-4.1 -3.56,-4.1 ; -4.06,-4.1 -3.56,-4.1 ; -3.56,-4.1 -3.56,-2.8 -3.56,-4.1 ; -2.79,-4.1 -2.79,-2.8 -2.79,-4.1 ; -2.79,-4.1 -2.29,-4.1 ; -2.79,-4.1 -2.29,-4.1 ; -2.79,4.1 -2.29,4.1 ; -2.79,4.1 -2.79,2.8 -2.79,4.1 ; -2.79,4.1 -2.29,4.1 ; -2.29,-4.1 -2.29,-2.8 -2.29,-4.1 ; -2.29,4.1 -2.29,2.8 -2.29,4.1 ; -1.52,-4.1 -1.52,-2.8 -1.52,-4.1 ; -1.52,-4.1 -1.02,-4.1 ; -1.52,-4.1 -1.02,-4.1 ; -1.52,4.1 -1.02,4.1 ; -1.52,4.1 -1.52,2.8 -1.52,4.1 ; -1.52,4.1 -1.02,4.1 ; -1.02,-4.1 -1.02,-2.8 -1.02,-4.1 ; -1.02,4.1 -1.02,2.8 -1.02,4.1 ; -0.25,-4.1 -0.25,-2.8 -0.25,-4.1 ; -0.25,-4.1 0.25,-4.1 ; -0.25,-4.1 0.25,-4.1 ; -0.25,4.1 0.25,4.1 ; -0.25,4.1 -0.25,2.8 -0.25,4.1 ; -0.25,4.1 0.25,4.1 ; 0.25,-4.1 0.25,-2.8 0.25,-4.1 ; 0.25,4.1 0.25,2.8 0.25,4.1 ; 1.02,-4.1 1.02,-2.8 1.02,-4.1 ; 1.02,-4.1 1.52,-4.1 ; 1.02,-4.1 1.52,-4.1 ; 1.02,4.1 1.52,4.1 ; 1.02,4.1 1.02,2.8 1.02,4.1 ; 1.02,4.1 1.52,4.1 ; 1.52,-4.1 1.52,-2.8 1.52,-4.1 ; 1.52,4.1 1.52,2.8 1.52,4.1 ; 2.29,-4.1 2.29,-2.8 2.29,-4.1 ; 2.29,-4.1 2.79,-4.1 ; 2.29,-4.1 2.79,-4.1 ; 2.29,4.1 2.79,4.1 ; 2.29,4.1 2.29,2.8 2.29,4.1 ; 2.29,4.1 2.79,4.1 ; 2.79,-4.1 2.79,-2.8 2.79,-4.1 ; 2.79,4.1 2.79,2.8 2.79,4.1 ; 3.56,-4.1 3.56,-2.8 3.56,-4.1 ; 3.56,-4.1 4.06,-4.1 ; 3.56,-4.1 4.06,-4.1 ; 3.56,4.1 4.06,4.1 ; 3.56,4.1 3.56,2.8 3.56,4.1 ; 3.56,4.1 4.06,4.1 ; 4.06,-4.1 4.06,-2.8 4.06,-4.1 ; 4.06,4.1 4.06,2.8 4.06,4.1 ; -5.25,-2.8 5.25,-2.8 5.25,2.8 -5.25,2.8 -5.25,-2.8
  text "'.Designator'" at -2,-0.5 h0.75
  text "1" at -4.06,-3.821 h1.5
  text "7" at 3.55,-3.925 h1.5
  text "8" at 3.485,2.985 h1.5
  text "16" at -4.33,2.985 h1.5
M16-Top Courtyard:
  lines w0.01: -5.5,-4.55 -5.5,4.55 5.5,4.55 5.5,-4.55 -5.5,-4.55
3D body: height 1.07, standoff 0.92, extent -4.06,-3.177 -3.56,-2.8
3D body: height 1.07, standoff 0, extent -4.06,-3.177 -3.56,-3.101
3D body: height 0.15, standoff 0, extent -4.06,-4.097 -3.56,-3.1
3D body: height 1.07, standoff 0.92, extent -2.79,-3.177 -2.29,-2.8
3D body: height 1.07, standoff 0, extent -2.79,-3.177 -2.29,-3.101
3D body: height 0.15, standoff 0, extent -2.79,-4.097 -2.29,-3.1
3D body: height 1.07, standoff 0.92, extent -1.52,-3.177 -1.02,-2.8
3D body: height 1.07, standoff 0, extent -1.52,-3.177 -1.02,-3.101
3D body: height 0.15, standoff 0, extent -1.52,-4.097 -1.02,-3.1
3D body: height 1.07, standoff 0.92, extent -0.25,-3.177 0.25,-2.8
3D body: height 1.07, standoff 0, extent -0.25,-3.177 0.25,-3.101
3D body: height 0.15, standoff 0, extent -0.25,-4.097 0.25,-3.1
3D body: height 1.07, standoff 0.92, extent 1.02,-3.177 1.52,-2.8
3D body: height 1.07, standoff 0, extent 1.02,-3.177 1.52,-3.101
3D body: height 0.15, standoff 0, extent 1.02,-4.097 1.52,-3.1
3D body: height 1.07, standoff 0.92, extent 2.29,-3.177 2.79,-2.8
3D body: height 1.07, standoff 0, extent 2.29,-3.177 2.79,-3.101
3D body: height 0.15, standoff 0, extent 2.29,-4.097 2.79,-3.1
3D body: height 1.07, standoff 0.92, extent 3.56,-3.177 4.06,-2.8
3D body: height 1.07, standoff 0, extent 3.56,-3.177 4.06,-3.101
3D body: height 0.15, standoff 0, extent 3.56,-4.097 4.06,-3.1
3D body: height 1.07, standoff 0.92, extent 3.56,2.8 4.06,3.177
3D body: height 1.07, standoff 0, extent 3.56,3.101 4.06,3.177
3D body: height 0.15, standoff 0, extent 3.56,3.1 4.06,4.097
3D body: height 1.07, standoff 0.92, extent 2.29,2.8 2.79,3.177
3D body: height 1.07, standoff 0, extent 2.29,3.101 2.79,3.177
3D body: height 0.15, standoff 0, extent 2.29,3.1 2.79,4.097
3D body: height 1.07, standoff 0.92, extent 1.02,2.8 1.52,3.177
3D body: height 1.07, standoff 0, extent 1.02,3.101 1.52,3.177
3D body: height 0.15, standoff 0, extent 1.02,3.1 1.52,4.097
3D body: height 1.07, standoff 0.92, extent -0.25,2.8 0.25,3.177
3D body: height 1.07, standoff 0, extent -0.25,3.101 0.25,3.177
3D body: height 0.15, standoff 0, extent -0.25,3.1 0.25,4.097
3D body: height 1.07, standoff 0.92, extent -1.52,2.8 -1.02,3.177
3D body: height 1.07, standoff 0, extent -1.52,3.101 -1.02,3.177
3D body: height 0.15, standoff 0, extent -1.52,3.1 -1.02,4.097
3D body: height 1.07, standoff 0.92, extent -2.79,2.8 -2.29,3.177
3D body: height 1.07, standoff 0, extent -2.79,3.101 -2.29,3.177
3D body: height 0.15, standoff 0, extent -2.79,3.1 -2.29,4.097
3D body: height 1.07, standoff 0.92, extent -4.06,2.8 -3.56,3.177
3D body: height 1.07, standoff 0, extent -4.06,3.101 -3.56,3.177
3D body: height 2, standoff 0, extent -5.25,-2.8 5.25,2.8
3D body: height 2.01, standoff 2, extent -4.631,-2.271 -3.931,-1.571
3D body: height 0.15, standoff 0, extent -4.06,3.1 -3.56,4.097

## ICC_SO14_8P75X6P20_P127_H1P75 [mm] "MCD-03383"
height 1.75
pads (14):
  rect 0.6x1.55 smd mask+0.05: 1(-3.81,-2.7) 2(-2.54,-2.7) 3(-1.27,-2.7) 4(0,-2.7) 5(1.27,-2.7) 6(2.54,-2.7) 7(3.81,-2.7) 8(3.81,2.7) 9(2.54,2.7) 10(1.27,2.7) 11(0,2.7) 12(-1.27,2.7) 13(-2.54,2.7) 14(-3.81,2.7)
Top Overlay:
  lines w0.12: -4.223,-1.95 cw(c-4.223,-1.8) -4.373,-1.8 -4.373,1.8 cw(c-4.223,1.8) -4.223,1.95 ; 4.223,-1.95 ccw(c4.223,-1.8) 4.373,-1.8 4.373,1.8 ccw(c4.223,1.8) 4.223,1.95
  text "1" at -4.6,-3.275 h1.5
M14-Top Assembly:
  drawing of 264 lines, arcs and shapes, not listed
  text "16" at -4.315,2 h1.5
  text "8" at 3.5,2 h1.5
  text "7" at 3.475,-3 h1.5
  text "1" at -3.94,-2.95 h1.5
  text "'.Designator'" at -2,-0.5 h0.75
M16-Top Courtyard:
  lines w0.01: -4.625,-3.625 4.625,-3.625 4.625,3.625 -4.625,3.625 -4.625,-3.625
3D body "User Library-so14-1.STEP": height 1.7, standoff 0, extent -4.4,-3 4.4,3

## ICC_SO28_18P10X7P60_P127 [mm]
height 2.65
pads (28):
  rect 0.8x2.02 smd mask+0.05: 1(-8.255,-4.59) 2(-6.985,-4.59) 3(-5.715,-4.59) 4(-4.445,-4.59) 5(-3.175,-4.59) 6(-1.905,-4.59) 7(-0.635,-4.59) 8(0.635,-4.59) 9(1.905,-4.59) 10(3.175,-4.59) 11(4.445,-4.59) 12(5.715,-4.59) 13(6.985,-4.59) 14(8.255,-4.59) 15(8.255,4.59) 16(6.985,4.59) 17(5.715,4.59) 18(4.445,4.59) 19(3.175,4.59) 20(1.905,4.59) 21(0.635,4.59) 22(-0.635,4.59) 23(-1.905,4.59) 24(-3.175,4.59) 25(-4.445,4.59) 26(-5.715,4.59) 27(-6.985,4.59) 28(-8.255,4.59)
Top Overlay:
  circle w0.12: c-8.25,-3 r0.375
  lines w0.12: -8.775,-3.8 -9.05,-3.8 -9.05,3.8 -8.775,3.8 ; 8.775,-3.8 9.05,-3.8 9.05,3.8 8.775,3.8
  text "1" at -9.175,-5.125 h1.5
M14-Top Assembly:
  circle w0.01: c-8.25,-3 r0.375
  lines w0.01: -8.509,-3.8 -8.509,-5.315 -8.001,-5.315 -8.001,-3.8 ; -8.509,3.8 -8.509,5.315 -8.001,5.315 -8.001,3.8 ; -7.239,-3.8 -7.239,-5.315 -6.731,-5.315 -6.731,-3.8 ; -7.239,3.8 -7.239,5.315 -6.731,5.315 -6.731,3.8 ; -5.969,-3.8 -5.969,-5.315 -5.461,-5.315 -5.461,-3.8 ; -5.969,3.8 -5.969,5.315 -5.461,5.315 -5.461,3.8 ; -4.699,-3.8 -4.699,-5.315 -4.191,-5.315 -4.191,-3.8 ; -4.699,3.8 -4.699,5.315 -4.191,5.315 -4.191,3.8 ; -3.429,-3.8 -3.429,-5.315 -2.921,-5.315 -2.921,-3.8 ; -3.429,3.8 -3.429,5.315 -2.921,5.315 -2.921,3.8 ; -2.159,-3.8 -2.159,-5.315 -1.651,-5.315 -1.651,-3.8 ; -2.159,3.8 -2.159,5.315 -1.651,5.315 -1.651,3.8 ; -0.889,-3.8 -0.889,-5.315 -0.381,-5.315 -0.381,-3.8 ; -0.889,3.8 -0.889,5.315 -0.381,5.315 -0.381,3.8 ; 0.381,-3.8 0.381,-5.315 0.889,-5.315 0.889,-3.8 ; 0.381,3.8 0.381,5.315 0.889,5.315 0.889,3.8 ; 1.651,-3.8 1.651,-5.315 2.159,-5.315 2.159,-3.8 ; 1.651,3.8 1.651,5.315 2.159,5.315 2.159,3.8 ; 2.921,-3.8 2.921,-5.315 3.429,-5.315 3.429,-3.8 ; 2.921,3.8 2.921,5.315 3.429,5.315 3.429,3.8 ; 4.191,-3.8 4.191,-5.315 4.699,-5.315 4.699,-3.8 ; 4.191,3.8 4.191,5.315 4.699,5.315 4.699,3.8 ; 5.461,-3.8 5.461,-5.315 5.969,-5.315 5.969,-3.8 ; 5.461,3.8 5.461,5.315 5.969,5.315 5.969,3.8 ; 6.731,-3.8 6.731,-5.315 7.239,-5.315 7.239,-3.8 ; 6.731,3.8 6.731,5.315 7.239,5.315 7.239,3.8 ; 8.001,-3.8 8.001,-5.315 8.509,-5.315 8.509,-3.8 ; 8.001,3.8 8.001,5.315 8.509,5.315 8.509,3.8 ; -9.05,-3.8 -9.05,3.8 9.05,3.8 9.05,-3.8 -9.05,-3.8
  text "'.Designator'" at -2,-0.5 h0.75
  text "1" at -8.475,-4.925 h1.5
  text "14" at 7.675,-4.925 h1.5
  text "15" at 7.725,4.085 h1.5
  text "28" at -8.875,4.185 h1.5
M16-Top Courtyard:
  lines w0.01: -9.25,-5.75 -9.25,3.75 -9.25,5.75 9.25,5.75 9.25,-5.75 8.6,-5.75 -9.25,-5.75
3D body "SO-28W.STEP": height 2.48, standoff 0, extent -8.965,-5.155 8.965,5.155
3D body: height 2.65, standoff 0, extent -9.049,-3.799 9.049,3.799

## ICC_SOIC8_3P91X4P90_P127_H1P75 [mm]
height 1.75
pads (8):
  rect 1.55x0.6 smd mask+0.05: 1(-2.7,1.905) 2(-2.7,0.635) 3(-2.7,-0.635) 4(-2.7,-1.905) 5(2.7,-1.905) 6(2.7,-0.635) 7(2.7,0.635) 8(2.7,1.905)
Top Overlay:
  lines w0.12: -2,-2.325 -2,-2.375 ccw(c-1.875,-2.375) -1.875,-2.5 1.875,-2.5 ccw(c1.875,-2.375) 2,-2.375 2,-2.325 ; -2,-1.486 -2,-1.054 ; -2,-0.216 -2,0.216 ; -2,1.054 -2,1.486 ; -2,2.325 -2,2.375 cw(c-1.875,2.375) -1.875,2.5 1.875,2.5 cw(c1.875,2.375) 2,2.375 2,2.325 ; 1.75,-2.35 -1.375,-2.35 cw(c-1.375,-2.225) -1.5,-2.225 -1.5,2.25 cw(c-1.4,2.25) -1.4,2.35 1.75,2.35 ; 2,-1.486 2,-1.054 ; 2,-0.216 2,0.216 ; 2,1.054 2,1.486
  text "1" at -3.25,2.675 h1.5
M14-Top Assembly:
  lines w0.01: -2,-2.155 -3.1,-2.155 -3.1,-1.655 -2,-1.655 ; -2,-0.885 -3.1,-0.885 -3.1,-0.385 -2,-0.385 ; -2,0.385 -3.1,0.385 -3.1,0.885 -2,0.885 ; -2,1.655 -3.1,1.655 -3.1,2.155 -2,2.155 ; 2,-2.155 3.1,-2.155 3.1,-1.655 2,-1.655 ; 2,-0.885 3.1,-0.885 3.1,-0.385 2,-0.385 ; 2,0.385 3.1,0.385 3.1,0.885 2,0.885 ; 2,1.655 3.1,1.655 3.1,2.155 2,2.155 ; -2,-2.375 ccw(c-1.875,-2.375) -1.875,-2.5 1.875,-2.5 ccw(c1.875,-2.375) 2,-2.375 2,2.375 ccw(c1.875,2.375) 1.875,2.5 -1.875,2.5 ccw(c-1.875,2.375) -2,2.375 -2,-2.375 ; -1.5,-2.25 ccw(c-1.375,-2.25) -1.375,-2.375 1.75,-2.375 ccw(c1.75,-2.25) 1.875,-2.25 1.875,2.25 ccw(c1.75,2.25) 1.75,2.375 -1.375,2.375 ccw(c-1.375,2.25) -1.5,2.25 -1.5,-2.25
  text "1" at -2.675,1.65 h0.75
  text "4" at -2.7,-2.15 h0.75
  text "5" at 2.4,-2.15 h0.75
  text "8" at 2.4,1.65 h0.75
  text "'.Designator'" at -2,-0.5 h0.75
M16-Top Courtyard:
  lines w0.01: -3.625,-2.7 3.625,-2.7 3.625,2.7 -3.625,2.7 -3.625,-2.7
3D body: height 1.75, standoff 0, extent -1.999,-2.5 1.999,2.5
3D body "SO8.STEP": height 1.7, standoff 0, extent -3,-2.45 3,2.45

## ICC_SOIC8_6P20X5P_EPAD_P127_H1P75 [mm]
height 1.75
pads (9):
  rect 1.52x0.6 smd mask+0.05: 1(-2.74,1.905) 2(-2.74,0.635) 3(-2.74,-0.635) 4(-2.74,-1.905) 5(2.74,-1.905) 6(2.74,-0.635) 7(2.74,0.635) 8(2.74,1.905)
  rect 2.3x2.3 smd mask+0.05: 9(0,0)
Top Overlay:
  circle w0.12: c-1.325,1.925 r0.25
  lines w0.12: -2,-2.375 -2,-2.5 2,-2.5 2,-2.375 ; -2,2.375 -2,2.5 2,2.5 2,2.375
  text "1" at -3.225,2.725 h1.5
M14-Top Assembly:
  circle w0.01: c-1.6,2.1 r0.26
  lines w0.01: -2,-2.16 -3.1,-2.16 -3.1,-1.65 -2,-1.65 ; -2,-0.89 -3.1,-0.89 -3.1,-0.38 -2,-0.38 ; -2,0.38 -3.1,0.38 -3.1,0.89 -2,0.89 ; -2,1.65 -3.1,1.65 -3.1,2.16 -2,2.16 ; 2,-2.16 3.1,-2.16 3.1,-1.65 2,-1.65 ; 2,-0.89 3.1,-0.89 3.1,-0.38 2,-0.38 ; 2,0.38 3.1,0.38 3.1,0.89 2,0.89 ; 2,1.65 3.1,1.65 3.1,2.16 2,2.16 ; -2,-2.5 -2,2.5 2,2.5 2,-2.5 -2,-2.5 ; -1.145,-1.145 1.145,-1.145 1.145,1.145 -1.145,1.145 -1.145,-1.145
  text "8" at 2.45,1.675 h0.75
  text "5" at 2.425,-2.15 h0.75
  text "1" at -2.675,1.656 h0.75
  text "4" at -2.725,-2.15 h0.75
  text "'.Designator'" at -2,-0.5 h0.75
M16-Top Courtyard:
  lines w0.01: -3.65,-2.75 3.65,-2.75 3.65,2.75 -3.65,2.75 -3.65,-2.75
3D body: height 1.65, standoff 0, extent 2.301,1.652 2.55,2.16
3D body: height 0.25, standoff 0, extent 2.3,1.652 3.1,2.16
3D body: height 1.65, standoff 1.4, extent 2,1.651 2.55,2.159
3D body: height 1.65, standoff 0, extent 2.301,0.382 2.55,0.89
3D body: height 0.25, standoff 0, extent 2.3,0.382 3.1,0.89
3D body: height 1.65, standoff 1.4, extent 2,0.381 2.55,0.889
3D body: height 1.65, standoff 0, extent 2.301,-0.888 2.55,-0.38
3D body: height 0.25, standoff 0, extent 2.3,-0.888 3.1,-0.38
3D body: height 1.65, standoff 1.4, extent 2,-0.889 2.55,-0.381
3D body: height 1.65, standoff 0, extent 2.301,-2.158 2.55,-1.65
3D body: height 0.25, standoff 0, extent 2.3,-2.158 3.1,-1.65
3D body: height 1.65, standoff 1.4, extent 2,-2.159 2.55,-1.651
3D body: height 1.65, standoff 0, extent -2.55,-2.158 -2.301,-1.65
3D body: height 0.25, standoff 0, extent -3.1,-2.158 -2.3,-1.65
3D body: height 1.65, standoff 1.4, extent -2.55,-2.159 -2,-1.651
3D body: height 1.65, standoff 0, extent -2.55,-0.888 -2.301,-0.38
3D body: height 0.25, standoff 0, extent -3.1,-0.888 -2.3,-0.38
3D body: height 1.65, standoff 1.4, extent -2.55,-0.889 -2,-0.381
3D body: height 1.65, standoff 0, extent -2.55,0.382 -2.301,0.89
3D body: height 0.25, standoff 0, extent -3.1,0.382 -2.3,0.89
3D body: height 1.65, standoff 1.4, extent -2.55,0.381 -2,0.889
3D body: height 1.65, standoff 0, extent -2.55,1.652 -2.301,2.16
3D body: height 0.25, standoff 0, extent -3.1,1.652 -2.3,2.16
3D body: height 1.65, standoff 1.4, extent -2.55,1.651 -2,2.159
3D body: height 1.76, standoff 1.75, extent -1.85,1.85 -1.35,2.35
3D body: height 1.75, standoff 0, extent -2,-2.5 2,2.5

## ICC_SOIC8_6P20X5P_P127_H1P75 [mm]
height 1.75
pads (8):
  rect 1.52x0.6 smd mask+0.05: 1(-2.74,1.905) 2(-2.74,0.635) 3(-2.74,-0.635) 4(-2.74,-1.905) 5(2.74,-1.905) 6(2.74,-0.635) 7(2.74,0.635) 8(2.74,1.905)
Top Overlay:
  circle w0.12: c-1.325,1.925 r0.25
  lines w0.12: -2,-2.375 -2,-2.5 2,-2.5 2,-2.375 ; -2,2.375 -2,2.5 2,2.5 2,2.375
  text "1" at -3.225,2.725 h1.5
M14-Top Assembly:
  circle w0.01: c-1.6,2.1 r0.26
  lines w0.01: -2,-2.16 -3.1,-2.16 -3.1,-1.65 -2,-1.65 ; -2,-0.89 -3.1,-0.89 -3.1,-0.38 -2,-0.38 ; -2,0.38 -3.1,0.38 -3.1,0.89 -2,0.89 ; -2,1.65 -3.1,1.65 -3.1,2.16 -2,2.16 ; 2,-2.16 3.1,-2.16 3.1,-1.65 2,-1.65 ; 2,-0.89 3.1,-0.89 3.1,-0.38 2,-0.38 ; 2,0.38 3.1,0.38 3.1,0.89 2,0.89 ; 2,1.65 3.1,1.65 3.1,2.16 2,2.16 ; -2,-2.5 -2,2.5 2,2.5 2,-2.5 -2,-2.5
  text "8" at 2.45,1.675 h0.75
  text "5" at 2.425,-2.15 h0.75
  text "1" at -2.675,1.656 h0.75
  text "4" at -2.725,-2.15 h0.75
  text "'.Designator'" at -2,-0.5 h0.75
M16-Top Courtyard:
  lines w0.01: -3.65,-2.75 3.65,-2.75 3.65,2.75 -3.65,2.75 -3.65,-2.75
3D body: height 1.65, standoff 0, extent 2.301,1.652 2.55,2.16
3D body: height 0.25, standoff 0, extent 2.3,1.652 3.1,2.16
3D body: height 1.65, standoff 1.4, extent 2,1.651 2.55,2.159
3D body: height 1.65, standoff 0, extent 2.301,0.382 2.55,0.89
3D body: height 0.25, standoff 0, extent 2.3,0.382 3.1,0.89
3D body: height 1.65, standoff 1.4, extent 2,0.381 2.55,0.889
3D body: height 1.65, standoff 0, extent 2.301,-0.888 2.55,-0.38
3D body: height 0.25, standoff 0, extent 2.3,-0.888 3.1,-0.38
3D body: height 1.65, standoff 1.4, extent 2,-0.889 2.55,-0.381
3D body: height 1.65, standoff 0, extent 2.301,-2.158 2.55,-1.65
3D body: height 0.25, standoff 0, extent 2.3,-2.158 3.1,-1.65
3D body: height 1.65, standoff 1.4, extent 2,-2.159 2.55,-1.651
3D body: height 1.65, standoff 0, extent -2.55,-2.158 -2.301,-1.65
3D body: height 0.25, standoff 0, extent -3.1,-2.158 -2.3,-1.65
3D body: height 1.65, standoff 1.4, extent -2.55,-2.159 -2,-1.651
3D body: height 1.65, standoff 0, extent -2.55,-0.888 -2.301,-0.38
3D body: height 0.25, standoff 0, extent -3.1,-0.888 -2.3,-0.38
3D body: height 1.65, standoff 1.4, extent -2.55,-0.889 -2,-0.381
3D body: height 1.65, standoff 0, extent -2.55,0.382 -2.301,0.89
3D body: height 0.25, standoff 0, extent -3.1,0.382 -2.3,0.89
3D body: height 1.65, standoff 1.4, extent -2.55,0.381 -2,0.889
3D body: height 1.65, standoff 0, extent -2.55,1.652 -2.301,2.16
3D body: height 0.25, standoff 0, extent -3.1,1.652 -2.3,2.16
3D body: height 1.65, standoff 1.4, extent -2.55,1.651 -2,2.159
3D body: height 1.76, standoff 1.75, extent -1.85,1.85 -1.35,2.35
3D body: height 1.75, standoff 0, extent -2,-2.5 2,2.5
